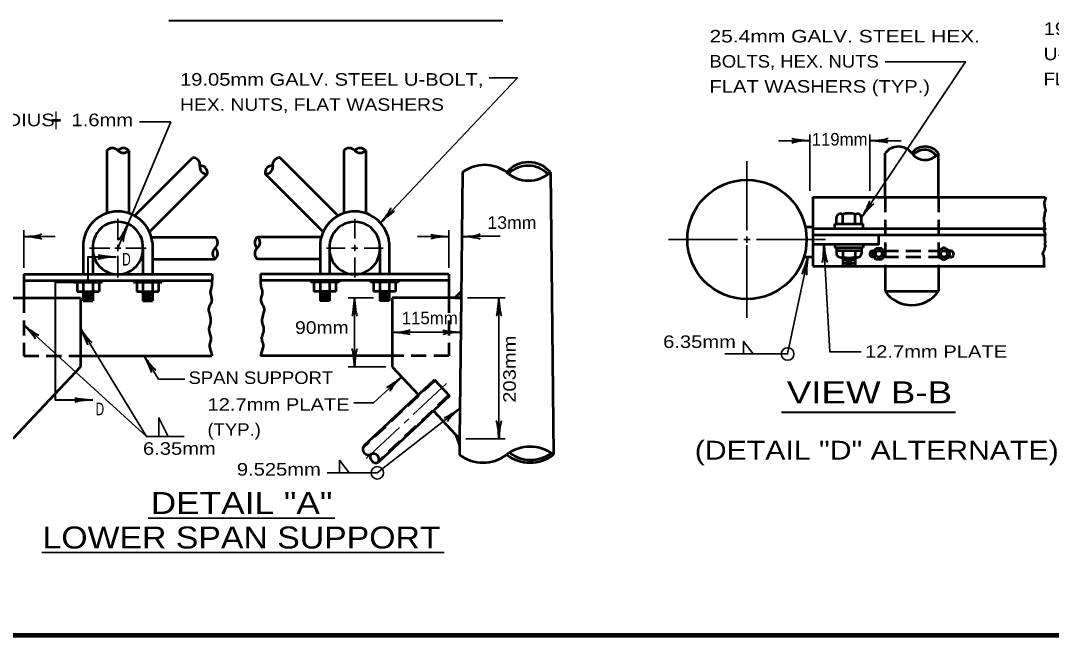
# Model space of a CAD drawing. Extents: x -35 to 821, y -13 to 531.
# Drawn here: x 258.8 to 455.8, y -1 to 116.6 of the extents above; entities that cross this region are included whole.
import ezdxf
from ezdxf.enums import TextEntityAlignment as Align

# ---------------------------------------------------------------- set-up
doc = ezdxf.new("R2010")
doc.units = 0
doc.header["$LTSCALE"] = 0.96
doc.linetypes.add('MEDIUM_DASHED', pattern=[4.5, 3, -1.5])
doc.layers.add('1', color=7, linetype='Continuous', lineweight=53)

msp = doc.modelspace()

# ---------------------------------------------------------------- linework, layer by layer
at = {"layer": '1', "lineweight": 40}
for p, q in [((287.144, 116.566), (350.991, 116.566)), ((404.257, 41.6985), (437.4955, 41.6985))]:
    msp.add_line(p, q, dxfattribs=at)
at = {"layer": '1', "lineweight": 35}
for p, q in [((277.3715, 73.0624), (287.5088, 97.1855)), ((287.5088, 97.1855), (281.5088, 97.1855)), ((409.6424, 83.9953), (409.6424, 94.7953)), ((421.1223, 83.9953), (421.1223, 94.7953)), ((403.6424, 93.5953), (409.6424, 93.5953)), ((421.1223, 93.5953), (427.1223, 93.5953)), ((397.6421, 89.6953), (397.6421, 76.4953)), ((277.3715, 78.6811), (277.3715, 74.5624)), ((322.6559, 78.6811), (322.6559, 74.8624)), ((259.3715, 69.2576), (259.3715, 76.4576)), ((259.3715, 75.2576), (265.3715, 75.2576)), ((340.6559, 75.2576), (334.6559, 75.2576)), ((340.6559, 69.2576), (340.6559, 76.4576)), ((344.4918, 75.3268), (350.4918, 75.3268)), ((271.9585, 73.0624), (275.8715, 73.0624)), ((277.3715, 73.6624), (277.3715, 72.4624)), ((278.8715, 73.0624), (282.7845, 73.0624)), ((320.8559, 73.0624), (317.2429, 73.0624)), ((323.2559, 73.0624), (322.0559, 73.0624)), ((322.6559, 73.6624), (322.6559, 72.4624)), ((328.0689, 73.0624), (324.4559, 73.0624)), ((382.6421, 74.6953), (395.8421, 74.6953)), ((397.0421, 74.6953), (397.6421, 74.6953)), ((397.6421, 74.6953), (397.6421, 74.0953)), ((397.6421, 73.6095), (397.6421, 59.6953)), ((399.4421, 74.6953), (412.6421, 74.6953)), ((277.3715, 71.5624), (277.3715, 67.4437)), ((322.6559, 71.2624), (322.6559, 67.4437)), ((326.2559, 63.5577), (321.4158, 63.5577)), ((322.6158, 63.5577), (322.6158, 50.3577)), ((344.2159, 63.5577), (351.4159, 63.5577)), ((350.2159, 63.5577), (350.2159, 36.5559)), ((329.8158, 56.9577), (342.9425, 56.9577)), ((328.6158, 50.3577), (321.4158, 50.3577)), ((340.2107, 47.1439), (333.8547, 41.2032)), ((326.9703, 30.0809), (342.7806, 42.3959)), ((332.978, 40.384), (332.1014, 39.5646)), ((331.2247, 38.7452), (324.8689, 32.8047)), ((282.8238, 36.9965), (290.0238, 36.9965)), ((343.9157, 36.5559), (351.4159, 36.5559)), ((326.9703, 30.0809), (317.3703, 30.0809)), ((283.1982, 21.4088), (318.871, 21.4088)), ((262.8409, 14.8141), (339.7356, 14.8141))]:
    msp.add_line(p, q, dxfattribs=at)
at = {"layer": '1'}
for p, q in [((275.2715, 91.7179), (275.2715, 79.7179)), ((279.4715, 91.7179), (279.4715, 79.7179)), ((320.5559, 91.7179), (320.5559, 79.7179)), ((324.7559, 91.7179), (324.7559, 79.7179)), ((424.0421, 82.7953), (424.0421, 91.1953)), ((434.2421, 82.7953), (434.2421, 91.1953)), ((280.565, 79.2394), (291.6192, 90.2936)), ((319.4624, 79.2394), (308.4082, 90.2936)), ((283.4055, 76.1762), (294.4854, 87.2561)), ((316.6219, 76.1762), (305.542, 87.2561)), ((343.2828, 87.5563), (343.0159, 63.5577)), ((360.0824, 87.5563), (360.6824, 33.5563)), ((410.2421, 82.7953), (454.6421, 82.7953)), ((410.2421, 82.7953), (410.2421, 69.5953)), ((414.7421, 77.6953), (414.7421, 78.8953)), ((415.9421, 77.6953), (415.9421, 79.4953)), ((418.3421, 77.6953), (418.3421, 79.4953)), ((419.5421, 77.6953), (419.5421, 78.8953)), ((408.7866, 77.0953), (410.2421, 77.0953)), ((414.4421, 76.7953), (414.4421, 77.6953)), ((414.4421, 77.6953), (419.8421, 77.6953)), ((419.8421, 76.7953), (419.8421, 77.6953)), ((283.7708, 75.1624), (295.9715, 75.1624)), ((316.2566, 75.1624), (304.0559, 75.1624)), ((410.2421, 76.7953), (454.6421, 76.7953)), ((410.2421, 75.5953), (454.6421, 75.5953)), ((270.7715, 74.0576), (270.7715, 68.0576)), ((283.9715, 74.0576), (283.9715, 68.0576)), ((316.0559, 74.0576), (316.0559, 68.0576)), ((329.2559, 74.0576), (329.2559, 68.0576)), ((414.4421, 73.7953), (414.4421, 73.1953)), ((414.4421, 73.1953), (419.8421, 73.1953)), ((414.7421, 73.1953), (414.7421, 71.9953)), ((419.5421, 73.1953), (419.5421, 71.9953)), ((419.8421, 73.7953), (419.8421, 73.1953)), ((423.4421, 73.0011), (422.2561, 73.0011)), ((272.5715, 72.8576), (272.5715, 68.0576)), ((282.1715, 72.8576), (282.1715, 68.0576)), ((283.9715, 70.9624), (295.9715, 70.9624)), ((316.0559, 70.9624), (304.0559, 70.9624)), ((317.8559, 72.8576), (317.8559, 68.0576)), ((327.4559, 72.8576), (327.4559, 68.0576)), ((408.554, 71.3953), (410.2421, 71.3953)), ((414.7421, 72.5953), (419.5421, 72.5953)), ((415.9421, 72.5953), (415.9421, 69.5953)), ((416.5421, 71.0953), (417.7421, 71.0953)), ((418.3421, 72.5953), (418.3421, 69.5953)), ((434.2421, 72.5441), (434.2421, 71.3581)), ((435.2921, 70.7581), (434.2421, 71.3581)), ((436.3421, 71.3581), (435.2921, 70.7581)), ((436.3421, 72.5441), (436.3421, 71.3581)), ((410.2421, 69.5953), (454.6421, 69.5953)), ((415.9421, 70.7953), (418.3421, 70.7953)), ((415.9421, 70.1953), (418.3421, 70.1953)), ((416.5421, 70.4953), (417.7421, 70.4953)), ((416.5421, 69.8953), (417.7421, 69.8953)), ((423.4421, 70.9011), (422.2561, 70.9011)), ((424.0421, 69.5953), (424.0421, 64.7953)), ((434.2421, 69.5953), (434.2421, 64.7953)), ((259.3715, 68.0576), (295.3715, 68.0576)), ((259.3715, 68.0576), (259.3715, 63.5577)), ((340.6559, 68.0576), (304.6559, 68.0576)), ((340.6559, 68.0576), (340.6559, 63.5577)), ((259.3715, 66.8576), (295.3715, 66.8576)), ((268.9715, 66.8576), (268.9715, 66.5576)), ((268.9715, 66.5576), (274.3715, 66.5576)), ((269.5715, 66.5576), (269.5715, 64.7576)), ((270.7715, 66.5576), (270.7715, 62.9576)), ((272.5715, 66.5576), (272.5715, 62.9576)), ((273.7715, 66.5576), (273.7715, 64.7576)), ((274.3715, 66.8576), (274.3715, 66.5576)), ((280.3715, 66.8576), (280.3715, 66.5576)), ((280.3715, 66.5576), (285.7715, 66.5576)), ((280.9715, 66.5576), (280.9715, 64.7576)), ((282.1715, 66.5576), (282.1715, 62.9576)), ((283.9715, 66.5576), (283.9715, 62.9576)), ((285.1715, 66.5576), (285.1715, 64.7576)), ((285.7715, 66.8576), (285.7715, 66.5576)), ((340.6559, 66.8576), (304.6559, 66.8576)), ((314.2559, 66.8576), (314.2559, 66.5576)), ((319.6559, 66.5576), (314.2559, 66.5576)), ((314.8559, 66.5576), (314.8559, 64.7576)), ((316.0559, 66.5576), (316.0559, 62.9576)), ((317.8559, 66.5576), (317.8559, 62.9576)), ((319.0559, 66.5576), (319.0559, 64.7576)), ((319.6559, 66.8576), (319.6559, 66.5576)), ((325.6559, 66.8576), (325.6559, 66.5576)), ((331.0559, 66.5576), (325.6559, 66.5576)), ((326.2559, 66.5576), (326.2559, 64.7576)), ((327.4559, 66.5576), (327.4559, 62.9576)), ((329.2559, 66.5576), (329.2559, 62.9576)), ((330.4559, 66.5576), (330.4559, 64.7576)), ((331.0559, 66.8576), (331.0559, 66.5576)), ((257.0115, 63.5577), (270.2116, 63.5577)), ((269.5715, 64.7576), (273.7715, 64.7576)), ((270.2116, 63.5577), (270.2116, 50.3577)), ((270.7715, 64.1576), (272.5715, 64.1576)), ((270.7715, 63.5576), (272.5715, 63.5576)), ((271.0715, 64.4576), (272.2715, 64.4576)), ((271.0715, 63.8576), (272.2715, 63.8576)), ((271.0715, 63.2576), (272.2715, 63.2576)), ((280.9715, 64.7576), (285.1715, 64.7576)), ((282.1715, 64.1576), (283.9715, 64.1576)), ((282.1715, 63.5576), (283.9715, 63.5576)), ((282.4715, 64.4576), (283.6715, 64.4576)), ((282.4715, 63.8576), (283.6715, 63.8576)), ((282.4715, 63.2576), (283.6715, 63.2576)), ((319.0559, 64.7576), (314.8559, 64.7576)), ((317.8559, 64.1576), (316.0559, 64.1576)), ((317.8559, 63.5576), (316.0559, 63.5576)), ((317.5559, 64.4576), (316.3559, 64.4576)), ((317.5559, 63.8576), (316.3559, 63.8576)), ((317.5559, 63.2576), (316.3559, 63.2576)), ((330.4559, 64.7576), (326.2559, 64.7576)), ((329.2559, 64.1576), (327.4559, 64.1576)), ((329.2559, 63.5576), (327.4559, 63.5576)), ((328.9559, 64.4576), (327.7559, 64.4576)), ((328.9559, 63.8576), (327.7559, 63.8576)), ((328.9559, 63.2576), (327.7559, 63.2576)), ((329.8158, 63.5577), (329.8158, 50.3577)), ((343.0159, 63.5577), (329.8158, 63.5577)), ((343.0159, 63.5577), (342.7157, 36.556)), ((343.0158, 63.5577), (343.0292, 64.7576)), ((424.0421, 64.7953), (434.2421, 64.7953)), ((270.7715, 62.9576), (272.5715, 62.9576)), ((282.1715, 62.9576), (283.9715, 62.9576)), ((317.8559, 62.9576), (316.0559, 62.9576)), ((329.2559, 62.9576), (327.4559, 62.9576)), ((270.2116, 52.4386), (295.3715, 52.4386)), ((329.8158, 52.4386), (304.6559, 52.4386)), ((270.2116, 50.3577), (257.3117, 36.5559)), ((329.8158, 50.3577), (334.8318, 44.991)), ((337.9002, 47.8588), (324.3114, 35.1584)), ((337.9002, 47.8588), (340.7681, 44.7903)), ((340.7681, 44.7903), (327.1796, 32.0897)), ((337.6998, 41.9225), (342.7157, 36.5559)), ((342.7155, 36.556), (342.682, 33.5399)), ((342.7023, 35.3562), (342.7156, 36.5561))]:
    msp.add_line(p, q, dxfattribs=at)
at = {"layer": '1', "linetype": 'MEDIUM_DASHED'}
for p, q in [((424.0421, 82.7953), (424.0421, 69.5953)), ((434.2421, 82.7953), (434.2421, 69.5953)), ((423.7032, 72.5441), (434.2421, 72.5441)), ((423.7032, 71.3581), (434.2421, 71.3581)), ((338.0026, 47.7492), (324.199, 34.8481)), ((340.6656, 44.8998), (327.292, 32.4001))]:
    msp.add_line(p, q, dxfattribs=at)
at = {"layer": '1', "lineweight": 158}
msp.add_line((814.3112, -1.0154), (22.7112, -1.0154), dxfattribs=at)
at = {"layer": '1', "lineweight": 35}
for points in [[(419.5421, 78.8953), (439.433, 108.7092), (424.0888, 108.7092)], [(327.5551, 77.8962), (353.7805, 105.5992), (348.3676, 105.5992)], [(397.6421, 75.2953), (397.6421, 74.6953), (398.2421, 74.6953)], [(276.7715, 73.0624), (277.3715, 73.0624), (277.9715, 73.0624)], [(412.3408, 73.7953), (413.4611, 53.2487), (419.4611, 53.2487)], [(409.3171, 71.3953), (405.4015, 52.8092), (393.4015, 52.8092)], [(259.3715, 58.3974), (282.8238, 36.9965), (270.2116, 57.7322)], [(397.0015, 52.8092), (397.0015, 55.2092), (398.8015, 52.8092)], [(282.3951, 52.4386), (285.1385, 48.0103), (290.2057, 48.0103)], [(331.6347, 48.4116), (326.2609, 43.4935), (322.4587, 43.4935)], [(285.2238, 36.9965), (285.2238, 40.5965), (287.0238, 36.9965)], [(319.7703, 30.0809), (319.7703, 32.4809), (321.5703, 30.0809)]]:
    msp.add_lwpolyline(points, dxfattribs=at)
at = {"layer": '1'}
for points in [[(410.2421, 73.7953), (422.8421, 73.7953), (422.8421, 75.5953)], [(422.2561, 70.9011), (421.6561, 71.9511), (422.2561, 73.0011)], [(423.4421, 73.0011), (424.0421, 71.9511), (423.4421, 70.9011)], [(434.2421, 72.5441), (435.2921, 73.1441), (436.3421, 72.5441)], [(343.0292, 64.7576), (341.8159, 63.5577), (343.0159, 63.5577)], [(342.7156, 36.5561), (341.896, 37.4331), (342.7022, 35.3563)]]:
    msp.add_lwpolyline(points, dxfattribs=at)
at = {"layer": '1', "lineweight": 40}
for points in [[(265.4116, 66.5576), (271.6715, 66.5576), (271.6715, 71.3576), (277.0715, 71.3576)], [(265.4116, 66.5576), (265.4116, 44.0221), (272.6116, 44.0221)]]:
    msp.add_lwpolyline(points, dxfattribs=at)
at = {"layer": '1', "linetype": 'MEDIUM_DASHED'}
for points in [[(259.3715, 63.5577), (259.3715, 52.4386), (270.2116, 52.4386)], [(340.6559, 63.5577), (340.6559, 52.4386), (329.8158, 52.4386)]]:
    msp.add_lwpolyline(points, dxfattribs=at)
at = {"layer": '1'}
for centre, radius in [((397.6421, 74.6953), 11.4), ((422.8491, 71.9511), 0.6), ((435.2921, 71.9511), 0.6)]:
    msp.add_circle(centre, radius, dxfattribs=at)
at = {"layer": '1', "lineweight": 35}
for centre in [(405.4015, 52.8092), (326.9703, 30.0809)]:
    msp.add_circle(centre, 1.2, dxfattribs=at)
at = {"layer": '1'}
for centre, radius, start, end in [((276.3215, 90.7228), 1.4466, 43.46312, 136.53688), ((278.4215, 90.7228), 1.4466, 43.46312, 136.53688), ((278.4215, 92.712), 1.4466, 223.46312, 316.53688), ((321.6059, 90.7228), 1.4466, 43.46312, 136.53688), ((323.7059, 90.7238), 1.4466, 43.46312, 136.53688), ((323.7059, 92.713), 1.4466, 223.46312, 316.53687), ((426.5921, 89.2625), 3.1997, 37.16004, 142.83996), ((431.6921, 89.2625), 3.1997, 37.16004, 142.83996), ((431.6921, 93.1281), 3.1997, 217.16004, 322.83996), ((431.5872, 89.1008), 2.763, 36.24736, 140.76859), ((291.784, 89.0136), 1.2905, 349.34003, 97.33783), ((294.3206, 88.5361), 1.2905, 169.34003, 277.33783), ((293.2171, 87.4949), 1.2905, 349.34003, 97.33783), ((306.8103, 87.4949), 1.2905, 82.66217, 190.65997), ((305.7068, 88.5361), 1.2905, 262.66217, 10.65997), ((308.2434, 89.0136), 1.2905, 82.66217, 190.65997), ((347.4824, 81.9366), 7.0158, 53.22658, 126.77342), ((355.8824, 83.9482), 5.537, 40.66498, 139.33502), ((355.776, 83.4804), 5.333, 43.96833, 134.65588), ((355.8824, 92.3409), 6.3665, 228.72298, 311.27702), ((277.3715, 73.4294), 6.6298, 5.43705, 174.56295), ((322.6559, 73.4294), 6.6298, 5.43705, 174.56295), ((415.5332, 78.8131), 0.7954, 59.06287, 174.06723), ((417.1421, 75.964), 3.7297, 71.23152, 108.76847), ((418.751, 78.8131), 0.7954, 5.93277, 120.93713), ((277.3715, 73.2639), 4.8172, 355.16125, 184.83875), ((322.6559, 73.2639), 4.8172, 355.16125, 184.83875), ((295.1262, 74.1124), 1.348, 308.8354, 51.1646), ((304.8996, 74.1124), 1.348, 128.8354, 231.1646), ((303.2106, 74.1124), 1.348, 308.8354, 51.1646), ((277.3715, 72.8609), 4.8172, 175.16125, 4.83875), ((296.8152, 72.0124), 1.348, 128.8354, 231.1646), ((295.1262, 72.0124), 1.348, 308.8354, 51.1646), ((304.9012, 72.0124), 1.348, 128.8354, 231.1646), ((322.6559, 72.8609), 4.8172, 175.16125, 4.83875), ((415.5332, 72.0775), 0.7954, 185.93277, 300.93712), ((417.1421, 74.9266), 3.7297, 251.23153, 288.76848), ((418.751, 72.0775), 0.7954, 239.06287, 354.06723), ((421.7153, 71.9511), 0.5976, 82.89428, 277.10571), ((436.5704, 71.9254), 0.5976, 262.89429, 97.10572), ((429.1421, 68.3487), 6.2158, 214.86649, 325.13351), ((325.2845, 34.6305), 1.1071, 151.522, 294.60765), ((326.7186, 33.0961), 1.1071, 151.522, 294.60765), ((326.2065, 32.6175), 1.1071, 331.522, 114.60765), ((347.182, 39.4418), 7.4218, 232.67566, 307.32433), ((356.182, 27.638), 7.4218, 52.67567, 127.32434), ((356.182, 39.458), 7.4218, 232.67566, 307.32433), ((356.2824, 39.1816), 6.6284, 232.97178, 306.38302)]:
    msp.add_arc(centre, radius, start, end, dxfattribs=at)
at = {"layer": '1', "lineweight": 40}
for centre, major_axis, ratio, start_param, end_param in [((408.333, 93.2637), (2.1428, 0.1874), 0.122415, 0.89635335, 3.14159265), ((408.333, 93.2637), (2.1428, 0.1874), 0.122415, 0.89635335, 3.14159265), ((408.2978, 93.8492), (2.1077, -0.2108), 0.07063, 3.14071475, 5.41810995), ((408.2978, 93.8492), (2.1077, -0.2108), 0.07063, 3.14071475, 5.41810995), ((422.4669, 93.3414), (-2.1077, 0.2108), 0.07063, 3.14071475, 5.41810995), ((422.4317, 93.9269), (-2.1428, -0.1874), 0.122415, 0.89635335, 3.14159265), ((419.993, 80.1686), (-1.0334, -1.8865), 0.122415, 0.89635335, 3.14159265), ((420.4996, 79.8729), (1.3451, 1.6364), 0.07063, 6.28230741, 8.55970261), ((328.2145, 79.0751), (-1.3371, -1.685), 0.122415, 0.89635335, 3.14159265), ((328.6639, 78.6981), (-1.6021, -1.3858), 0.07063, 3.14071475, 5.41810995), ((278.5545, 76.5329), (1.0109, 1.8615), 0.07063, 3.14071475, 5.41810995), ((279.1079, 76.3385), (0.6574, 2.0481), 0.122415, 0.89635335, 3.14159265), ((260.7161, 75.0037), (-2.1077, 0.2108), 0.07063, 3.14071475, 5.41810995), ((260.7161, 75.0037), (-2.1077, 0.2108), 0.07063, 3.14071475, 5.41810995), ((260.6809, 75.5892), (-2.1428, -0.1874), 0.122415, 0.89635335, 3.14159265), ((260.6809, 75.5892), (-2.1428, -0.1874), 0.122415, 0.89635335, 3.14159265), ((339.3465, 74.926), (2.1428, 0.1874), 0.122415, 0.89635335, 3.14159265), ((339.3113, 75.5115), (2.1077, -0.2108), 0.07063, 3.14071475, 5.41810995), ((344.504, 75.0037), (-2.1077, 0.2108), 0.07063, 3.14071475, 5.41810995), ((344.4688, 75.5892), (-2.1428, -0.1874), 0.122415, 0.89635335, 3.14159265), ((412.1605, 72.4389), (-0.0957, -2.1161), 0.07063, 6.28230741, 8.55970261), ((412.7432, 72.5059), (-0.3038, 2.1295), 0.122415, 0.89635335, 3.14159265), ((275.7621, 71.026), (2.1428, 0.1874), 0.122415, 0.89635335, 3.14159265), ((275.7269, 71.6115), (2.1077, -0.2108), 0.07063, 3.14071475, 5.41810995), ((408.7914, 70.1319), (-0.6408, -2.019), 0.07063, 6.28230741, 8.55970261), ((409.3716, 70.0456), (0.2584, 2.1354), 0.122415, 0.89635335, 3.14159265), ((322.3619, 62.2131), (0.2108, 2.1077), 0.07063, 3.14071475, 5.41810995), ((322.3619, 62.2131), (0.2108, 2.1077), 0.07063, 3.14071475, 5.41810995), ((322.9474, 62.2483), (-0.1874, 2.1428), 0.122415, 0.89635335, 3.14159265), ((322.9474, 62.2483), (-0.1874, 2.1428), 0.122415, 0.89635335, 3.14159265), ((349.962, 62.2131), (0.2108, 2.1077), 0.07063, 3.14071475, 5.41810995), ((349.962, 62.2131), (0.2108, 2.1077), 0.07063, 3.14071475, 5.41810995), ((350.5475, 62.2483), (-0.1874, 2.1428), 0.122415, 0.89635335, 3.14159265), ((350.5475, 62.2483), (-0.1874, 2.1428), 0.122415, 0.89635335, 3.14159265), ((260.1936, 57.3035), (1.4149, -1.5764), 0.07063, 6.28230741, 8.55970261), ((260.5622, 57.7597), (-1.7092, 1.306), 0.122415, 0.89635335, 3.14159265), ((270.6934, 56.4515), (0.9152, -1.9103), 0.07063, 6.28230741, 8.55970261), ((270.6934, 56.4515), (0.9152, -1.9103), 0.07063, 6.28230741, 8.55970261), ((271.1753, 56.7857), (-1.2736, 1.7334), 0.122415, 0.89635335, 3.14159265), ((271.1753, 56.7857), (-1.2736, 1.7334), 0.122415, 0.89635335, 3.14159265), ((331.1252, 57.2893), (-2.1428, -0.1874), 0.122415, 0.89635335, 3.14159265), ((331.1252, 57.2893), (-2.1428, -0.1874), 0.122415, 0.89635335, 3.14159265), ((341.5979, 57.2116), (2.1077, -0.2108), 0.07063, 3.14071475, 5.41810995), ((331.1604, 56.7038), (-2.1077, 0.2108), 0.07063, 3.14071475, 5.41810995), ((331.1604, 56.7038), (-2.1077, 0.2108), 0.07063, 3.14071475, 5.41810995), ((341.6331, 56.6261), (2.1428, 0.1874), 0.122415, 0.89635335, 3.14159265), ((322.2842, 51.6671), (0.1874, -2.1428), 0.122415, 0.89635335, 3.14159265), ((322.8697, 51.7023), (-0.2108, -2.1077), 0.07063, 3.14071475, 5.41810995), ((282.8874, 51.1618), (0.9308, -1.9028), 0.07063, 6.28230741, 8.55970261), ((283.3666, 51.5001), (-1.2878, 1.7229), 0.122415, 0.89635335, 3.14159265), ((330.4714, 47.6911), (-1.6972, -1.2675), 0.07063, 6.28230741, 8.55970261), ((330.8926, 47.283), (1.4543, 1.5849), 0.122415, 0.89635335, 3.14159265), ((271.3022, 43.6905), (2.1428, 0.1874), 0.122415, 0.89635335, 3.14159265), ((271.267, 44.276), (2.1077, -0.2108), 0.07063, 3.14071475, 5.41810995), ((341.5638, 41.77), (1.7924, 1.1289), 0.07063, 3.14071475, 5.41810995), ((341.9513, 41.3297), (1.5754, 1.4646), 0.122415, 0.89635335, 3.14159265), ((349.8843, 37.8653), (0.1874, -2.1428), 0.122415, 0.89635335, 3.14159265), ((350.4698, 37.9005), (-0.2108, -2.1077), 0.07063, 3.14071475, 5.41810995)]:
    msp.add_ellipse(centre, major_axis=major_axis, ratio=ratio, start_param=start_param, end_param=end_param, dxfattribs=at)
at = {"layer": '1'}
for points in [[(454.6421, 82.7953), (454.6781, 82.3091), (454.559, 82.1305), (454.4796, 81.7732), (454.4995, 81.2968), (454.5987, 80.7608), (454.7178, 80.2844), (454.6781, 80.0462), (454.5392, 79.6492), (454.5392, 79.3911), (454.4995, 79.2323), (454.4201, 78.9743), (454.3804, 78.6765), (454.3606, 78.3986), (454.3606, 78.2597), (454.4598, 77.9024), (454.5193, 77.5053), (454.4796, 77.2076), (454.44, 76.9892), (454.6421, 76.7953), (454.4201, 76.3342), (454.4598, 76.1952), (454.5789, 76.0364), (454.5789, 75.8578), (454.6582, 75.6394), (454.6421, 75.5953), (454.559, 74.6667), (454.559, 74.6072), (454.6384, 74.3094), (454.5789, 74.0911), (454.5392, 73.9124), (454.5987, 73.6544), (454.6582, 73.436), (454.5193, 72.9993), (454.4598, 72.7214), (454.2614, 72.3244), (454.1621, 71.9869), (454.301, 71.6098), (454.3804, 71.1929), (454.3804, 71.0341), (454.3804, 70.7959), (454.4201, 70.4783), (454.3804, 70.2798), (454.3804, 70.121), (454.4201, 69.9026), (454.3804, 69.7438), (454.6421, 69.5953)], [(295.3715, 68.0576), (295.3844, 67.586), (295.3715, 66.8576), (295.3001, 65.7023), (295.0472, 64.6339), (295.3001, 63.4249), (295.1877, 62.6096), (294.738, 61.6256), (294.738, 60.9227), (294.8785, 60.501), (295.1034, 59.3482), (295.0472, 58.6453), (294.8223, 57.9425), (294.8785, 56.9303), (295.1596, 55.5245), (294.8785, 54.5967), (294.991, 53.7814), (295.1877, 53.1629), (295.3715, 52.4386)], [(304.6559, 68.0576), (304.643, 67.586), (304.6559, 66.8576), (304.7273, 65.7023), (304.9802, 64.6339), (304.7273, 63.4249), (304.8397, 62.6096), (305.2894, 61.6256), (305.2894, 60.9227), (305.1489, 60.501), (304.924, 59.3482), (304.9802, 58.6453), (305.2051, 57.9425), (305.1489, 56.9303), (304.8678, 55.5245), (305.1489, 54.5967), (305.0364, 53.7814), (304.8397, 53.1629), (304.6559, 52.4386)]]:
    msp.add_spline(points, degree=3, dxfattribs=at)

# ---------------------------------------------------------------- texts
for s, height, width, p in [('25.4mm GALV. STEEL HEX.', 2.4, 1.25, (390.4748, 112.3824)), ('19.05mm GALV. STEEL', 2.4, 1.2, (454.356, 113.8082)), ('U-BOLTS, HEX. NUTS,', 2.4, 1.15, (454.356, 109.0082)), ('BOLTS, HEX. NUTS', 2.4, 1.1, (390.4748, 107.5824)), ('19.05mm GALV. STEEL U-BOLT,', 2.4, 1.2, (289.2569, 104.1143)), ('FLAT WASHERS', 2.4, 1.1, (454.356, 104.2082)), ('FLAT WASHERS (TYP.)', 2.4, 1.2, (390.4748, 102.7824)), ('HEX. NUTS, FLAT WASHERS', 2.4, 1.15, (289.2569, 99.3143)), ('CHORD RADIUS   1.6mm', 2.4, 1.2, (235.5632, 96.3723)), ('+', 4.8, 0.55, (264.5358, 95.1771)), ('13mm', 2.4, 1.05, (348.0322, 76.7407)), ('D', 2.4, 0.7, (278.2051, 69.7234)), ('90mm', 2.4, 1.15, (311.2482, 56.6672)), ('6.35mm', 2.4, 1.2, (381.6152, 53.951)), ('12.7mm PLATE', 2.4, 1.2, (420.2009, 52.072)), ('SPAN SUPPORT', 2.4, 1.1, (290.8875, 47.0689)), ('VIEW B-B', 4.2, 1.25, (405.2518, 43.3769)), ('D', 2.4, 0.7, (273.1322, 41.0881)), ('12.7mm PLATE', 2.4, 1.2, (294.5109, 41.954)), ('(TYP.)', 2.4, 1.1, (294.5109, 37.154)), ('6.35mm', 2.4, 1.2, (282.1837, 33.5271)), ('(DETAIL "D" ALTERNATE)', 3.6, 1.2, (387.6569, 32.6056)), ('9.525mm', 2.4, 1.2, (300.1261, 29.5456))]:
    msp.add_text(s, height=height, dxfattribs=dict(at, width=width)).set_placement(p)
for s, p in [('119mm', (410.0011, 92.6694)), ('115mm', (331.6524, 58.4868))]:
    msp.add_text(s, height=2.4, dxfattribs=at).set_placement(p)
at = {"layer": '1', "width": 1.2}
msp.add_text('203mm', height=2.4, rotation=90, dxfattribs=at).set_placement((353.4511, 43.4753))
at = {"layer": '1'}
for s, width, p in [('DETAIL "A"', 1.2, (301.0197, 22.2074)), ('LOWER SPAN SUPPORT', 1.15, (301.0199, 15.6074))]:
    msp.add_text(s, height=4.2, dxfattribs=dict(at, width=width)).set_placement(p, align=Align.CENTER)

doc.saveas('drawing.dxf')
